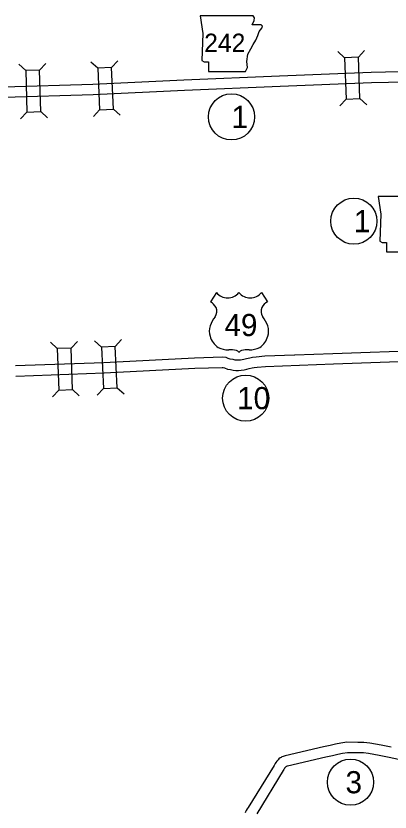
# Model space of a CAD drawing. Extents: x -939622 to -934222, y 1383701 to 1385301.
# Drawn here: x -935763.6 to -935731.4, y 1384029.5 to 1384098 of the extents above; entities that cross this region are included whole.
import ezdxf

# ---------------------------------------------------------------- set-up
doc = ezdxf.new("R2010")
doc.units = 0
for name, color, linetype in [('Level 10', 7, 'Continuous'), ('Level 15', 7, 'Continuous'), ('Level 20', 7, 'Continuous'), ('Level 21', 7, 'Continuous'), ('Level 22', 7, 'Continuous'), ('Level 27', 7, 'Continuous')]:
    doc.layers.add(name, color=color, linetype=linetype)

msp = doc.modelspace()

# ---------------------------------------------------------------- linework, layer by layer
at = {"layer": 'Level 10'}
for points in [[(-935764.625, 1384091.871), (-935756.982, 1384092.107), (-935749.153, 1384092.479), (-935740.924, 1384092.818), (-935733.056, 1384093.132), (-935725.693, 1384093.297)], [(-935764.598, 1384090.971), (-935756.947, 1384091.207), (-935749.114, 1384091.58), (-935740.887, 1384091.919), (-935733.028, 1384092.232), (-935725.693, 1384092.397)], [(-935731.33, 1384035.125), (-935732.188, 1384035.292), (-935733.159, 1384035.483), (-935733.676, 1384035.535), (-935734.209, 1384035.53), (-935735.135, 1384035.548), (-935735.67, 1384035.476), (-935736.123, 1384035.379), (-935736.578, 1384035.273), (-935737.159, 1384035.148), (-935740.461, 1384034.373), (-935740.614, 1384034.335), (-935740.722, 1384034.286), (-935740.806, 1384034.241), (-935740.883, 1384034.2), (-935740.986, 1384034.117), (-935741.05, 1384034.049), (-935741.114, 1384033.972), (-935741.153, 1384033.931), (-935741.246, 1384033.822), (-935741.303, 1384033.715), (-935741.34, 1384033.658), (-935741.394, 1384033.559), (-935743.616, 1384029.949), (-935743.722, 1384029.832), (-935743.796, 1384029.692), (-935743.848, 1384029.574), (-935743.882, 1384029.478)], [(-935730.709, 1384034.062), (-935731.516, 1384034.244), (-935732.361, 1384034.409), (-935733.292, 1384034.592), (-935733.717, 1384034.635), (-935734.213, 1384034.63), (-935735.084, 1384034.646), (-935735.516, 1384034.589), (-935735.926, 1384034.5), (-935736.382, 1384034.394), (-935736.961, 1384034.27), (-935740.25, 1384033.498), (-935740.317, 1384033.482), (-935740.322, 1384033.479), (-935740.379, 1384033.449), (-935740.439, 1384033.376), (-935740.482, 1384033.331), (-935740.499, 1384033.311), (-935740.527, 1384033.258), (-935740.565, 1384033.2), (-935740.614, 1384033.109), (-935742.894, 1384029.405)]]:
    msp.add_lwpolyline(points, dxfattribs=at)
at = {"layer": 'Level 15'}
for points in [[(-935739.622, 1384068.836), (-935736.339, 1384068.956), (-935728.312, 1384069.238)], [(-935763.621, 1384067.917), (-935756.03, 1384068.186), (-935748.251, 1384068.58), (-935745.821, 1384068.663), (-935745.554, 1384068.626), (-935745.375, 1384068.56), (-935745.193, 1384068.5), (-935744.945, 1384068.462), (-935744.766, 1384068.413), (-935744.648, 1384068.406), (-935744.464, 1384068.405), (-935744.288, 1384068.408), (-935744.145, 1384068.427), (-935743.998, 1384068.465), (-935743.764, 1384068.535), (-935743.486, 1384068.595), (-935743.242, 1384068.647), (-935742.933, 1384068.667), (-935742.196, 1384068.741), (-935739.65, 1384068.835)], [(-935763.589, 1384067.017), (-935755.992, 1384067.287), (-935748.213, 1384067.681), (-935745.868, 1384067.761), (-935745.773, 1384067.748), (-935745.672, 1384067.711), (-935745.404, 1384067.622), (-935745.133, 1384067.58), (-935744.912, 1384067.52), (-935744.675, 1384067.506), (-935744.458, 1384067.505), (-935744.221, 1384067.509), (-935743.971, 1384067.542), (-935743.756, 1384067.598), (-935743.54, 1384067.662), (-935743.296, 1384067.715), (-935743.118, 1384067.753), (-935742.859, 1384067.77), (-935742.135, 1384067.843), (-935736.307, 1384068.057), (-935728.28, 1384068.339)]]:
    msp.add_lwpolyline(points, dxfattribs=at)
at = {"layer": 'Level 20'}
for p, q in [((-935735.345, 1384094.375), (-935735.926, 1384094.913)), ((-935734.158, 1384094.42), (-935733.62, 1384095.001)), ((-935761.563, 1384093.298), (-935761.021, 1384093.875)), ((-935756.563, 1384093.46), (-935757.149, 1384093.993)), ((-935755.377, 1384093.517), (-935754.844, 1384094.103)), ((-935762.751, 1384093.261), (-935763.328, 1384093.804)), ((-935735.21, 1384090.813), (-935735.748, 1384090.232)), ((-935734.023, 1384090.858), (-935733.442, 1384090.32)), ((-935761.453, 1384089.736), (-935760.876, 1384089.193)), ((-935756.394, 1384089.9), (-935756.927, 1384089.314)), ((-935755.207, 1384089.957), (-935754.621, 1384089.424)), ((-935762.641, 1384089.699), (-935763.183, 1384089.122)), ((-935760.036, 1384069.377), (-935760.615, 1384069.916)), ((-935758.849, 1384069.419), (-935758.309, 1384069.998)), ((-935756.24, 1384069.51), (-935756.826, 1384070.042)), ((-935755.053, 1384069.568), (-935754.521, 1384070.154)), ((-935759.91, 1384065.815), (-935760.449, 1384065.235)), ((-935758.722, 1384065.857), (-935758.143, 1384065.317)), ((-935756.066, 1384065.95), (-935756.598, 1384065.364)), ((-935754.88, 1384066.008), (-935754.293, 1384065.476))]:
    msp.add_line(p, q, dxfattribs=at)
for points in [[(-935735.345, 1384094.375), (-935735.21, 1384090.813), (-935734.023, 1384090.858), (-935734.158, 1384094.42)], [(-935761.453, 1384089.736), (-935761.563, 1384093.298), (-935762.751, 1384093.261), (-935762.641, 1384089.699)], [(-935755.207, 1384089.957), (-935755.377, 1384093.517), (-935756.563, 1384093.46), (-935756.394, 1384089.9)], [(-935760.036, 1384069.377), (-935759.91, 1384065.815), (-935758.722, 1384065.857), (-935758.849, 1384069.419)], [(-935754.88, 1384066.008), (-935755.053, 1384069.568), (-935756.24, 1384069.51), (-935756.066, 1384065.95)]]:
    msp.add_lwpolyline(points, close=True, dxfattribs=at)
at = {"layer": 'Level 21'}
for points in [[(-935747.752, 1384097.962), (-935747.524, 1384096.44), (-935747.625, 1384094.131), (-935747.422, 1384094.004), (-935747.041, 1384094.004), (-935747.041, 1384093.192), (-935743.844, 1384093.192), (-935743.692, 1384093.522), (-935743.742, 1384094.054), (-935743.666, 1384094.663), (-935743.387, 1384095.146), (-935743.209, 1384095.501), (-935742.956, 1384095.882), (-935742.803, 1384096.288), (-935742.677, 1384096.617), (-935742.448, 1384096.897), (-935742.397, 1384097.074), (-935742.499, 1384097.201), (-935743.286, 1384097.201), (-935743.108, 1384097.556), (-935743.083, 1384097.785), (-935743.188, 1384097.96)], [(-935732.444, 1384082.45), (-935732.215, 1384080.927), (-935732.317, 1384078.618), (-935732.114, 1384078.491), (-935731.733, 1384078.491), (-935731.733, 1384077.679), (-935728.536, 1384077.679), (-935728.383, 1384078.009), (-935728.434, 1384078.542), (-935728.358, 1384079.151), (-935728.079, 1384079.633), (-935727.901, 1384079.988), (-935727.648, 1384080.369), (-935727.495, 1384080.775), (-935727.368, 1384081.105), (-935727.14, 1384081.384), (-935727.089, 1384081.562), (-935727.191, 1384081.689), (-935727.977, 1384081.689), (-935727.8, 1384082.044), (-935727.774, 1384082.272), (-935727.88, 1384082.448)]]:
    msp.add_lwpolyline(points, close=True, dxfattribs=at)
at = {"layer": 'Level 22'}
for p, q in [((-935746.351, 1384074.192), (-935746.87, 1384073.389)), ((-935742.49, 1384074.192), (-935741.971, 1384073.389))]:
    msp.add_line(p, q, dxfattribs=at)
for centre, radius, start, end in [((-935745.384, 1384075.005), 1.264, 220.07504, 319.67012), ((-935743.457, 1384075.005), 1.264, 220.32988, 319.92496), ((-935747.549, 1384072.223), 1.349, 30.7809, 59.98827), ((-935741.293, 1384072.223), 1.349, 120.01173, 149.2191), ((-935747.252, 1384072.579), 0.925, 328.81046, 21.21077), ((-935741.589, 1384072.579), 0.925, 158.78923, 211.18954), ((-935744.834, 1384070.683), 2.157, 138.95648, 162.69135), ((-935744.008, 1384070.683), 2.157, 17.30865, 41.04352), ((-935745.546, 1384070.86), 1.426, 160.95764, 197.38186), ((-935743.296, 1384070.86), 1.426, 342.61814, 19.04236), ((-935745.314, 1384070.864), 1.65, 195.10743, 237.13119), ((-935743.528, 1384070.864), 1.65, 302.86881, 344.89257), ((-935745.283, 1384071.384), 2.118, 244.07708, 269.57785), ((-935745.234, 1384065.386), 3.88, 81.19416, 90.95387), ((-935744.749, 1384068.865), 0.372, 28.03422, 72.98637), ((-935744.093, 1384068.865), 0.372, 107.01363, 151.96578), ((-935743.607, 1384065.386), 3.88, 89.04613, 98.80584), ((-935743.558, 1384071.384), 2.118, 270.42215, 295.92292)]:
    msp.add_arc(centre, radius, start, end, dxfattribs=at)
at = {"layer": 'Level 27'}
for centre in [(-935745.059, 1384089.286), (-935734.542, 1384080.326), (-935743.844, 1384065.119), (-935734.836, 1384032.115)]:
    msp.add_circle(centre, 1.98, dxfattribs=at)

# ---------------------------------------------------------------- texts
at = {"layer": 'Level 21'}
msp.add_text('242', height=1.584, dxfattribs=at).set_placement((-935747.408, 1384094.855))
at = {"layer": 'Level 22'}
msp.add_text('49', height=1.9008, dxfattribs=at).set_placement((-935745.66, 1384070.45))
at = {"layer": 'Level 27'}
for s, height, p in [('1', 1.901, (-935745.059, 1384088.336)), ('1', 1.901, (-935734.542, 1384079.375)), ('10', 1.9008, (-935744.576, 1384064.169)), ('3', 1.901, (-935735.261, 1384031.165))]:
    msp.add_text(s, height=height, dxfattribs=at).set_placement(p)

doc.saveas('drawing.dxf')
